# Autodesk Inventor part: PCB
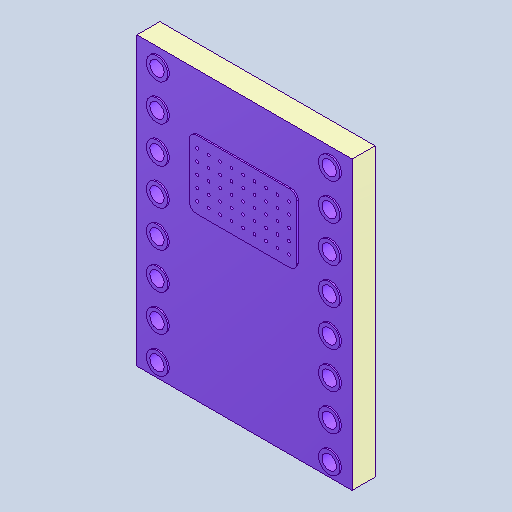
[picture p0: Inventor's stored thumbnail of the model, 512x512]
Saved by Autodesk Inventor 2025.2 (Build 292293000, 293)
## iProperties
Created: 2025-04
Part Number: PCB
Material: Generic
Description: PART--DESC
Document SubType Name: Modeling
Designer: BennF
Density: 1 g/cm^3
Appearance: Default
Author: BennF
Revision Number: NONE
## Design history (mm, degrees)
feature "Solid"
body "Solid1"
